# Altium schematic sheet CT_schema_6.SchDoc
size 368 x 245 mm
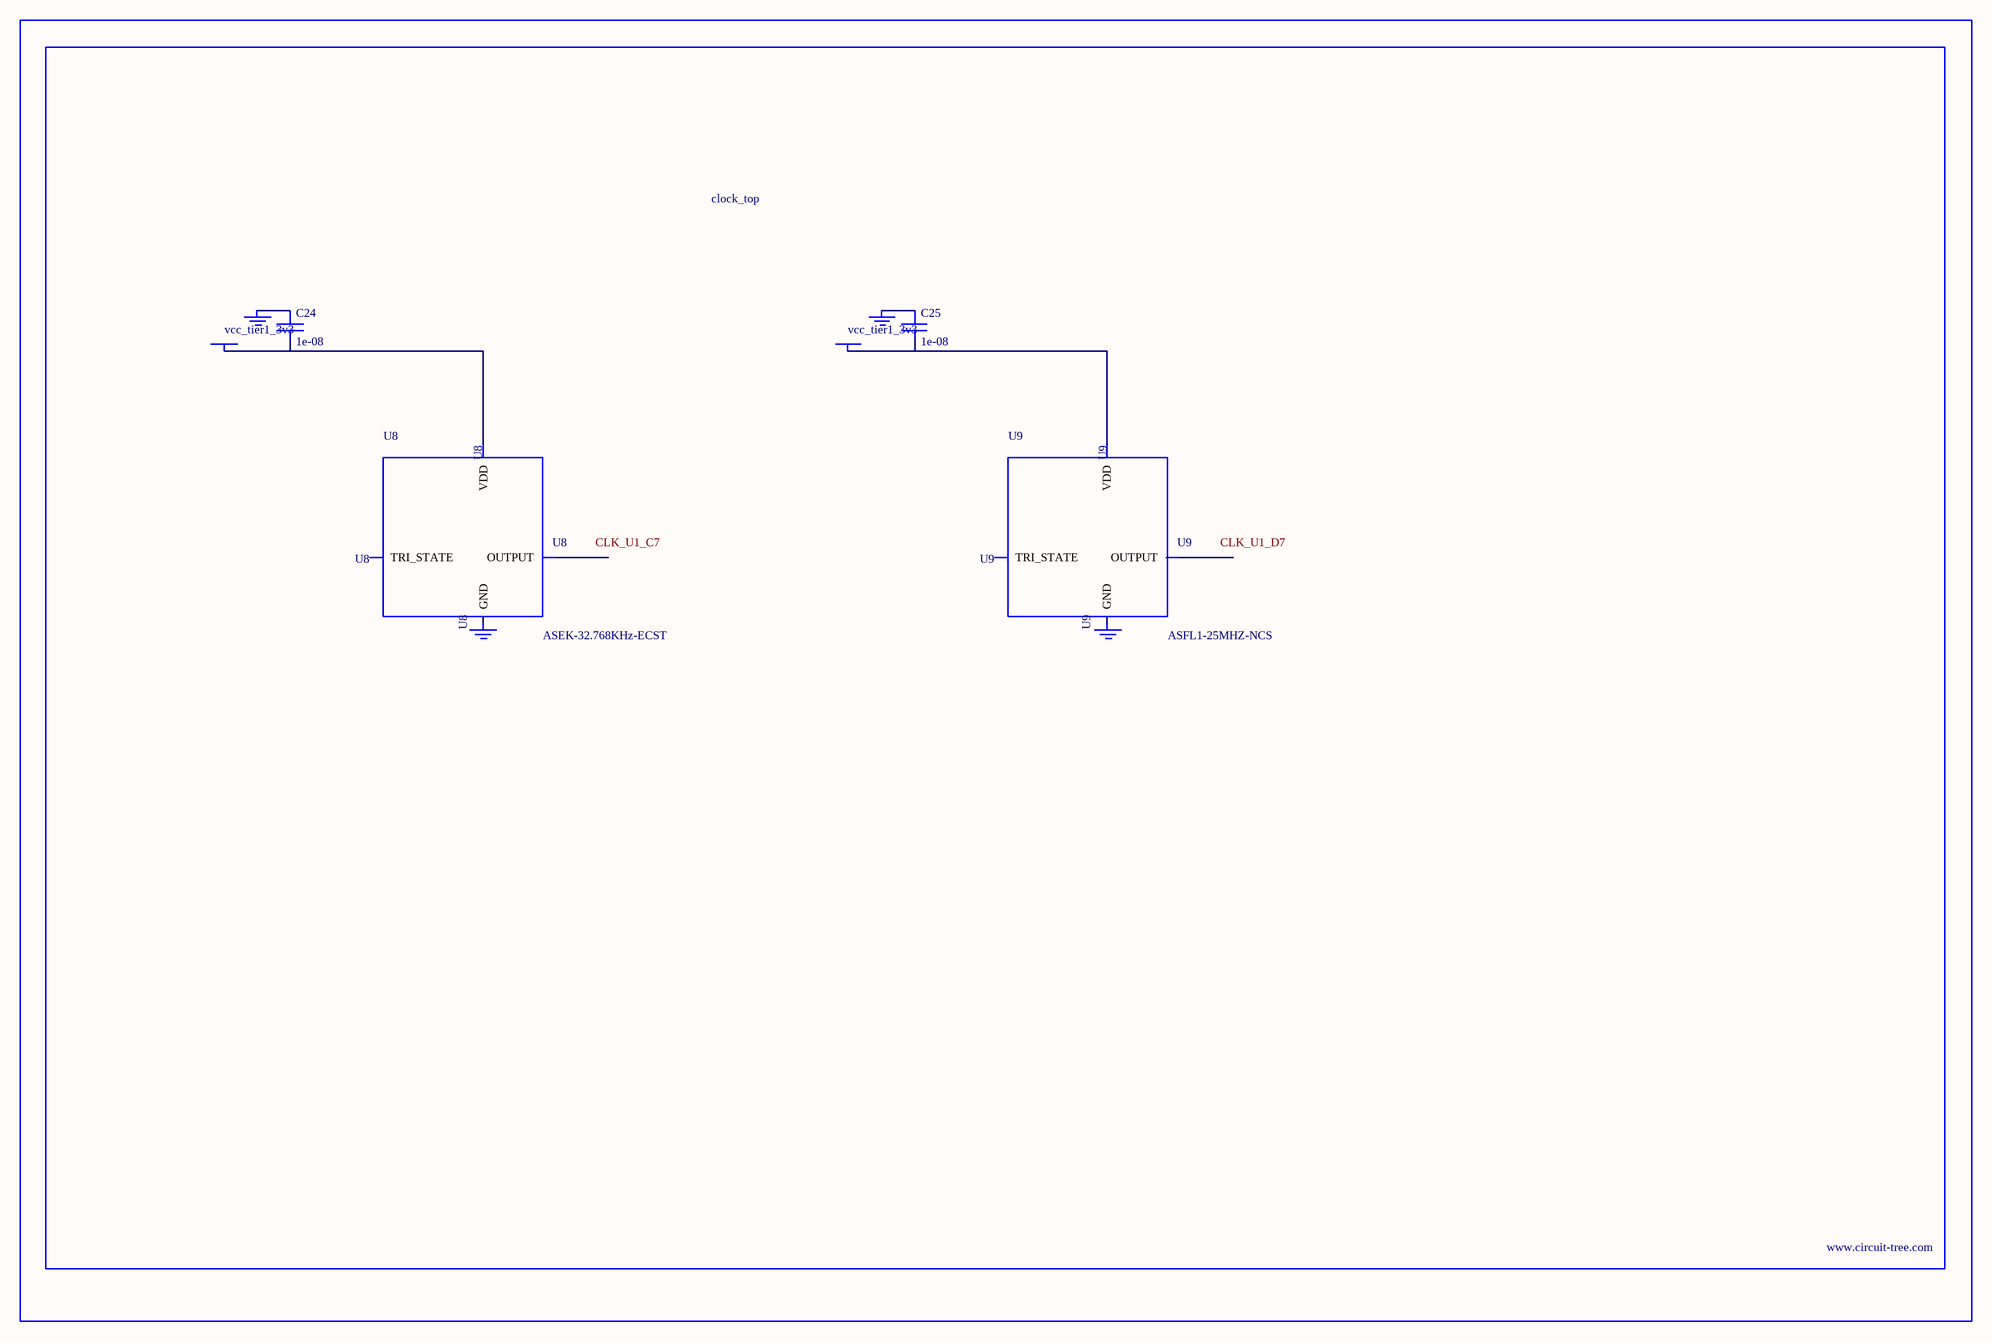
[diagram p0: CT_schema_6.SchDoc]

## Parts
BORDER5  (no value)
C24  1e-08  [C0402]
C25  1e-08  [C0402]
GND_INSTANCE_5_0  (no value)
GND_INSTANCE_5_1  (no value)
GND_INSTANCE_5_2  (no value)
GND_INSTANCE_5_3  (no value)
POWER_INSTANCE_5_0  vcc_tier1_3v3
POWER_INSTANCE_5_1  vcc_tier1_3v3
U8  ASEK-32.768KHz-ECST  [ASEK]
U9  ASFL1-25MHZ-NCS  [ASFL1]

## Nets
NetC24_1: C24.1 GND_INSTANCE_5_0.0(GND)
NetC24_2: C24.2 POWER_INSTANCE_5_0.0(PWR) U8.4(VDD)
NetC25_1: C25.1 GND_INSTANCE_5_2.0(GND)
NetC25_2: C25.2 POWER_INSTANCE_5_1.0(PWR) U9.4(VDD)

Not connected (* = marked no-connect by the designer): GND_INSTANCE_5_1 0(GND); GND_INSTANCE_5_3 0(GND); U8 1(TRI_STATE) 2(GND) 3(OUTPUT); U9 1(TRI_STATE) 2(GND) 3(OUTPUT)

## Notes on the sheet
- Labels drawn without touching a wire or pin: CLK_U1_C7, CLK_U1_D7

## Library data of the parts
BORDER5 = BORDER_PAGE5
C24 C25 = C0402C103K3RAC
GND_INSTANCE_5_0-GND_INSTANCE_5_3 = GND
POWER_INSTANCE_5_0 POWER_INSTANCE_5_1 = PWR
